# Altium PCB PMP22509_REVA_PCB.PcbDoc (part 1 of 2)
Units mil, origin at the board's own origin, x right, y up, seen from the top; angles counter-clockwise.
Board outline 3681.1 x 1505.91 mil, 2 copper layers (Top Layer, Bottom Layer), stack 62 mil thick; 70 components, 35 nets, 219 pads, 81 vias.
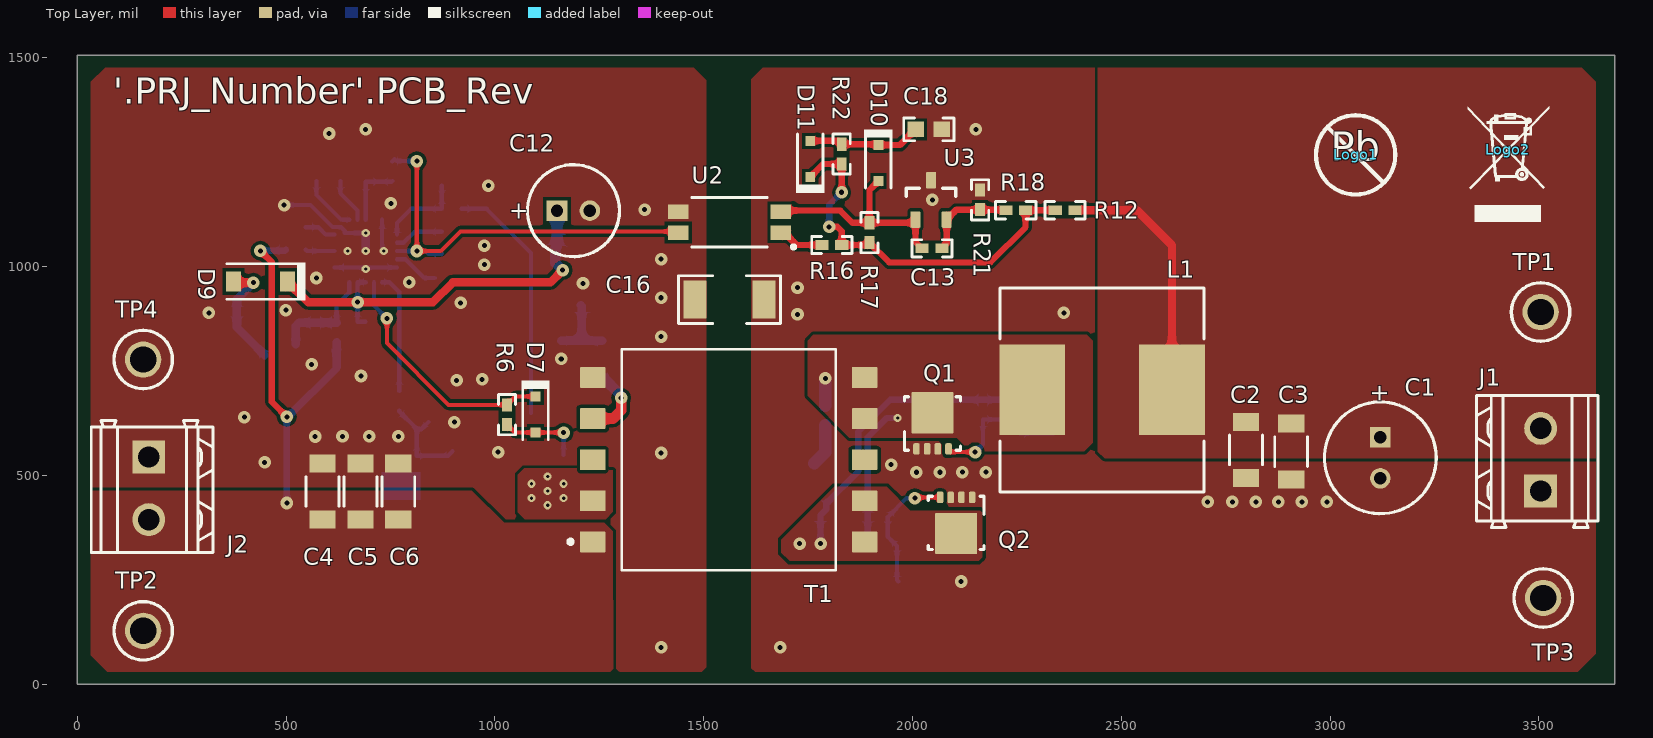
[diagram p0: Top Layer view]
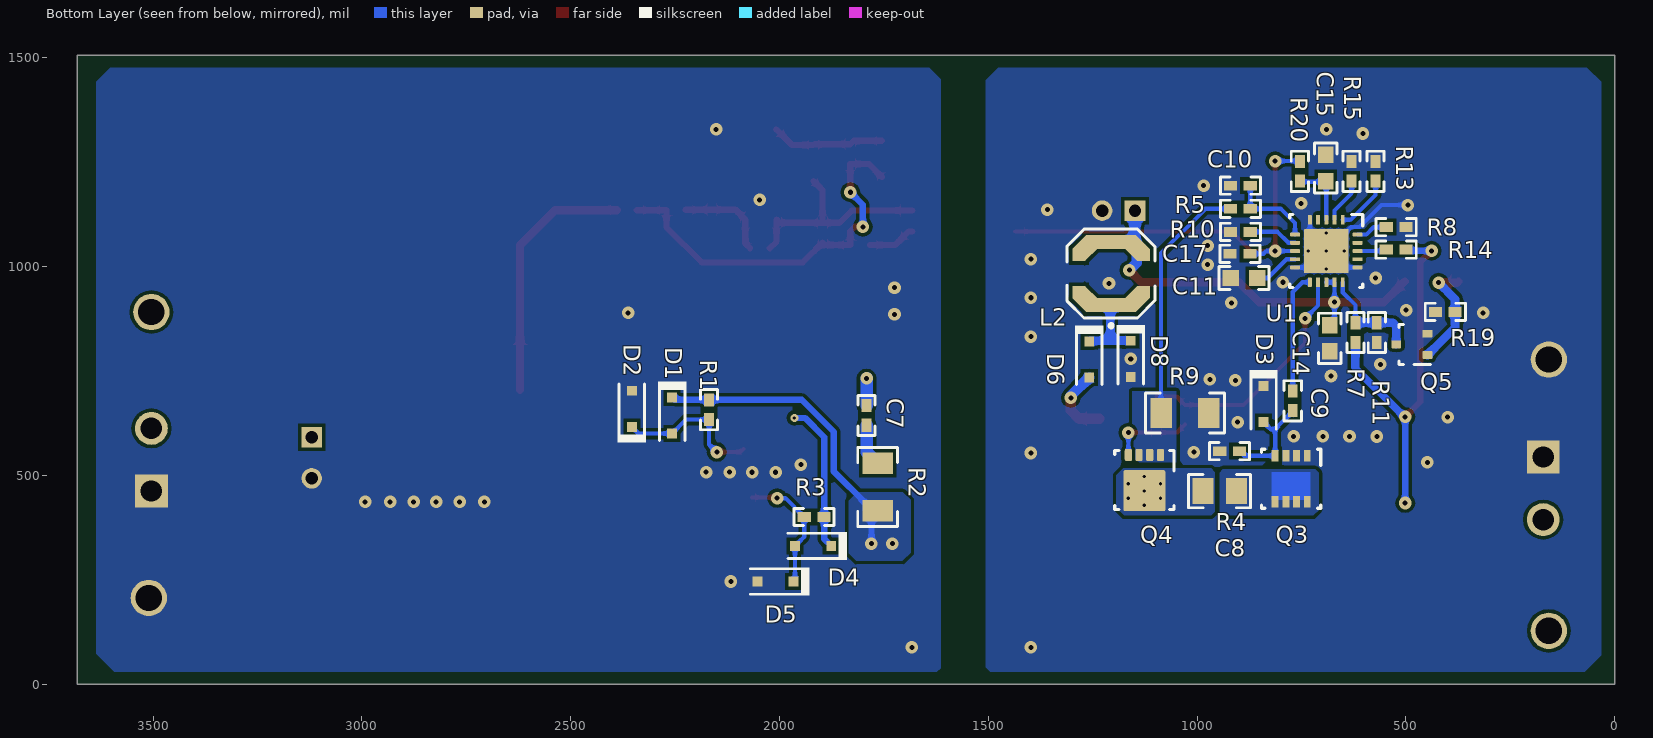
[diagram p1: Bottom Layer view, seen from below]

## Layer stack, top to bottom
Top Solder: solder mask 0.4, Solder Resist, Dk 3.5
Top Layer: signal copper 1.4
Dielectric1: core 59.2, FR-4, Dk 4.8
Bottom Layer: signal copper 1.4
Bottom Solder: solder mask 0.4, Solder Resist, Dk 3.5

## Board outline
0,0 0,1505.91 3681.1,1505.91 3681.1,0

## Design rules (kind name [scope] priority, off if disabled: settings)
AcuteAngle [All] p1: minimum=4.50000000000000E+0001 checktracksonly=FALSE
AssemblyTestPointUsage [All] p1: valid=2
BoardOutlineClearance BoardOutlineClearance_MountingHoles [OnCopper and InComponentClass('Mounting Holes')] p1: gap=25 ignorepadtopadclearanceinfootprint=FALSE
BoardOutlineClearance BoardOutlineClearance_Poly [OnCopper and InPoly] p2: gap=25 ignorepadtopadclearanceinfootprint=FALSE
BoardOutlineClearance [OnCopper and Not InComponentClass('Logo') and not InComponentClass('FiducialMark') and not InRegion(1000,500,4000,800)] p3: gap=25 ignorepadtopadclearanceinfootprint=FALSE
Clearance Clearance_Keepouts [((IsTrack Or IsArc) And Not InPoly) And IsFree and IsKeepOut vs ((IsTrack Or IsArc) And Not InPoly) And IsFree and IsKeepOut] p1: gap=0 ignorepadtopadclearanceinfootprint=FALSE
Clearance Clearance_Poly [InPolygon] p2: gap=8 ignorepadtopadclearanceinfootprint=FALSE except(0: Arc-Hole Track-Hole SMDPad-Hole THPad-Hole Via-Hole Fill-Hole Poly-Hole Region-Hole Text-Hole)
Clearance Clearance_FiducialMark [IsKeepOut and InComponentClass('FiducialMark') vs IsPad and InComponentClass('FiducialMark')] p3: gap=0 ignorepadtopadclearanceinfootprint=FALSE
Clearance [All] p4: gap=7.87 ignorepadtopadclearanceinfootprint=FALSE except(0: Arc-Hole Track-Hole SMDPad-Hole THPad-Hole Via-Hole Fill-Hole Poly-Hole Region-Hole Text-Hole)
ComponentClearance ComponentClearance_MountingHoles_FiducialMarks [InComponentClass('Mounting Holes') vs InComponentClass('FiducialMark')] p1: gap=50 collisioncheckmode=3 verticalgap=10 showdistances=FALSE
ComponentClearance ComponentClearance_Shunt [InComponentClass('Header') vs InComponentClass('Shunt')] p2: gap=0 collisioncheckmode=3 verticalgap=0 showdistances=FALSE
ComponentClearance ComponentClearance_Logo [InComponentClass('Logo')] p3: gap=50 collisioncheckmode=3 verticalgap=10 showdistances=FALSE
ComponentClearance ComponentClearance_ScrewToNut [(HasFootprint('NY PMS 440 0025 PH')) vs (HasFootprint('Keystone_1902C'))] p4: gap=5 collisioncheckmode=3 verticalgap=10 showdistances=FALSE
ComponentClearance ComponentClearance_MountingHoles [InComponentClass('Mounting Holes')] p5: gap=250 collisioncheckmode=3 verticalgap=100000 showdistances=FALSE
ComponentClearance ComponentClearance_SmallPassives [HasFootprint('0201*') or HasFootprint('0402*') or HasFootprint('0508') or HasFootprint('0603*') or HasFootprint('0612') or HasFootprint('0805*') or HasFootprint('0815*') or HasFootprint('0830*') or HasFootprint('1206*') or HasFootprint('1210*') or HasFootprint('1808*') or HasFootprint('1812*') or HasFootprint('1825*') or HasFootprint('2010*') or HasFootprint('2220*') or HasFootprint('2225*') or HasFootprint('2512*') or HasFootprint('2728*') or HasFootprint('3518*') vs HasFootprint('0201*') or HasFootprint('0402*') or HasFootprint('0508') or HasFootprint('0603*') or HasFootprint('0612') or HasFootprint('0805*') or HasFootprint('0815*') or HasFootprint('0830*') or HasFootprint('1206*') or HasFootprint('1210*') or HasFootprint('1808*') or HasFootprint('1812*') or HasFootprint('1825*') or HasFootprint('2010*') or HasFootprint('2220*') or HasFootprint('2225*') or HasFootprint('2512*') or HasFootprint('2728*') or HasFootprint('3518*')] p6: gap=14.96 collisioncheckmode=3 verticalgap=10 showdistances=FALSE
ComponentClearance ComponentClearance_THtoSMT [IsThruComponent vs IsSMTComponent] p7: gap=15 collisioncheckmode=3 verticalgap=30 showdistances=FALSE
ComponentClearance ComponentClearance_THtoTH [IsThruComponent vs IsThruComponent] p8: gap=15 collisioncheckmode=3 verticalgap=30 showdistances=FALSE
ComponentClearance [All] p9: gap=15 collisioncheckmode=3 verticalgap=10 showdistances=FALSE
DiffPairsRouting [All] p1: maxlimit=100 minlimit=10 mostfreqgap=10 toplayer_minwidth=15 toplayer_maxwidth=15 toplayer_prefwidth=15 bottomlayer_minwidth=15 bottomlayer_maxwidth=15 bottomlayer_prefwidth=15 maxuncoupledlength=1000
FabricationTestPointUsage TestPointUsage [All] p1: valid=2 allowmultiple=FALSE
FabricationTestpoint Testpoint [All] p1: side=3 testpointundercomponent=TRUE minsize=40 maxsize=100 preferedsize=60 minholesize=0 maxholesize=40 preferedholesize=32 testpointgrid=1 allowsidetop=TRUE allowsidebottom=TRUE usegrid=TRUE gridtolerance=0.01
FanoutControl Fanout_LCC [IsLCC] p1: bgadir=Out bgaviamode=Centered fanoutstyle=Auto fanoutdirection=Alternating viagrid=1 // Fanout_LCC (Default Rule)
FanoutControl Fanout_BGA [IsBGA] p2: bgadir=Out bgaviamode=Centered fanoutstyle=Auto fanoutdirection=Alternating viagrid=1 // Fanout_BGA (Default Rule)
FanoutControl Fanout_Default [All] p4: bgadir=Out bgaviamode=Centered fanoutstyle=Auto fanoutdirection=Alternating viagrid=1 // Fanout_Default (Default Rule)
FanoutControl Fanout_Small [(CompPinCount < 5)] p5: bgadir=Out bgaviamode=Centered fanoutstyle=Auto fanoutdirection=OutThenIn viagrid=1 // Fanout_Small (Default Rule)
HoleSize [All] p1: absolutevalues=TRUE maxlimit=251 minlimit=7.87 maxpercent=80.000 minpercent=20.000
MinimumAnnularRing MinimumAnnularRing_ThermalPadVias [IsVia and InAnyComponent] p1: minimumring=5.91
MinimumAnnularRing [All] p2: minimumring=8
MinimumSolderMaskSliver MinimumSolderMaskSliver_Logo [InComponentClass('Logo') vs InComponentClass('Logo')] p1: minsoldermaskwidth=0.7
MinimumSolderMaskSliver [All] p2: minsoldermaskwidth=3.94
PlaneConnect [All] p1: planeconnectstyle=Direct reliefexpansion=10 reliefentries=4 reliefconductorwidth=10 reliefairgap=10
PolygonConnect [All] p1: connectstyle=Direct reliefconductorwidth=10 reliefentries=4 polygonreliefangle="90 Angle" airgapwidth=10
RoutingVias ThermalPadVias [IsVia and InAnyComponent] p1: holewidth=7.87 width=19.68 viastyle="Through Hole" minholewidth=7.87 minwidth=19.68 maxholewidth=12.99 maxwidth=23.62
RoutingVias [All] p2: holewidth=16 width=34 viastyle="Through Hole" minholewidth=7.87 minwidth=26 maxholewidth=40 maxwidth=65
SilkToBoardRegionClearance [Not ((IsComment or IsDesignator) And (Hide <> 'False')) and not InRegion(1000,500,4000,800)] p1:
SilkToSilkClearance SilkToSilkClearance_Pb-FreeLogo [(HasFootprint('Pb-Free_Overlay_Medium') OR HasFootprint('Pb-Free_Overlay_Small')) vs (HasFootprint('Pb-Free_Overlay_Medium') OR HasFootprint('Pb-Free_Overlay_Small'))] p1: silktosilkclearance=0
SilkToSilkClearance [All] p2: silktosilkclearance=4
SilkToSolderMaskClearance SilkToComponentPadClearance [IsPad and InAnycomponent] p1: minsilkscreentomaskgap=5 clearancetoexposedcopper=TRUE
SilkToSolderMaskClearance "Silk to Solder Mask Opening" [All] p2: minsilkscreentomaskgap=4 clearancetoexposedcopper=FALSE
SolderMaskExpansion [All] p1: expansion=1.97
Width [All] p1: maxlimit=100 minlimit=6 preferedwidth=10 checkconnectedcopper=TRUE
15 further rules are at their usual default settings.

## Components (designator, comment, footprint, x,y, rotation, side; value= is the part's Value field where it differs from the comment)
C1 "10ZLH330MEFC6.3X11" ZLH_630x1100 3120.08,542.26 r270 top value=330uF
C2 "GRM31CR71A226KE15L" 1206_180 2798.23,561.18 r270 top value=22uF
C3 "GRM31CR71A226KE15L" 1206_180 2906.5,557.15 r270 top value=22uF
C4 "C3216X7R1H475K160AC" 1206_180 587.06,461.69 r90 top value=4.7uF
C5 "C3216X7R1H475K160AC" 1206_180 677.73,461.69 r90 top value=4.7uF
C6 "C3216X7R1H475K160AC" 1206_180 768.68,461.69 r90 top value=4.7uF
C7 "CGA2B2X7R1H102K050BA" 0402 1791.37,643.7 r270 bottom value=1000pF
C8 "GRM21BR72A104KAC4L" 0805_HV 945.87,462.6 r180 bottom value=0.1uF
C9 "GRM155R71E104KE14D" 0402 770.67,678.88 r270 bottom value=0.1uF
C10 "GRM1555C1H101JA01D" 0402 896.09,1193.92 r180 bottom value=100pF
C11 "C1608X7R1H224K080AB" 0603 887.23,972.87 r0 bottom value=0.22uF
C12 "EKMG160ELL101ME11D" Chemi-Con_500x1100 1187.82,1134.13 r0 top value=100uF
C13 "GRM155R71H222KA01D" 0402 2046.54,1043.98 r180 top value=2200pF
C14 "CGA3E1X7R1V105K080AE" 0603 682.09,828.48 r90 bottom value=1uF
C15 "CGA3E1X7R1V105K080AE" 0603 691.58,1236.18 r270 bottom value=1uF
C16 "C1808C272KGRACTU" 1808 1561.64,921.28 r180 top value=2700pF
C17 "CGA2B2X7R1H102K050BA" 0402 897.07,1030.87 r0 bottom value=1000pF
C18 "CGA3E1X7R1V105K080AE" 0603 2038.78,1328.74 r180 top value=1uF
D1 "BAS316,115" SOD-323 2256.89,643.7 r270 bottom value=100V
D2 "SZMM3Z18VST1G" SOD-323 2353.35,659.45 r90 bottom value=18V
D3 "BAS316,115" SOD-323 840.69,671.26 r270 bottom value=100V
D4 "BAS316,115" SOD-323 1919.29,331.18 r0 bottom value=100V
D5 "SZMM3Z18VST1G" SOD-323 2009.18,246.06 r0 bottom value=18V
D6 "BAS316,115" SOD-323 1258,777.9 r270 bottom value=100V
D7 "BAS316,115" SOD-323 1096.95,646.01 r270 top value=100V
D8 "BAS316,115" SOD-323 1158.66,779.43 r270 bottom value=100V
D9 "MMSZ5245B-7-F" SOD-123 438.36,964.57 r180 top value=15V
D10 "BAS316,115" SOD-323 1918.23,1248.03 r270 top value=100V
D11 "BAS316,115" SOD-323 1754.92,1258.01 r90 top value=100V
J1 "691214310002" Wurth_691214310002 3503.94,537.74 r90 top
J2 "691214310002" Wurth_691214310002 170.92,469.32 r270 top
L1 "MSS1278T-472MLB" MSS1278T 2453.74,704.95 r0 top value=4.7uH
L2 "LPS4414-105MLB" LPS4414 1205.57,983.56 r90 bottom value=1mH
Logo1 "Pb-Free Symbol" Pb-Free_Overlay_Medium 3061.02,1267.68 r0 top
Logo2 "WEEE logo" WEEE_Minimum 3425.2,1279.53 r0 top
Q1 "CSD17579Q3A" DNH0008A 2047.64,624.65 r90 top value=30V
Q2 "CSD17579Q3A" DNH0008A 2104.23,386.59 r270 top value=30V
Q3 "FDMC2523P" MLP08S 774.43,492.13 r270 bottom value=-150V
Q4 "CSD19537Q3" DQG0008A 1125.98,489.15 r270 bottom value=100V
Q5 "MMBT3904WT1G" SOT-323 485.6,813.87 r0 bottom value="40 V"
R1 "CRCW040220R0JNED" 0402 2168.31,657.48 r90 bottom value=20
R2 "CRCW120610R0JNEA" 1206 1764.76,472.44 r90 bottom value=10
R3 "CRCW040220R0JNED" 0402 1917.07,400.41 r180 bottom value=20
R4 "CRCW040210K0FKED" 0402 922.07,558.07 r0 bottom value=10.0k
R5 "CRCW04021K00FKED" 0402 896.09,1138.57 r0 bottom value=1.00k
R6 "CRCW040220R0JNED" 0402 1028.95,645.42 r270 top value=20
R7 "CRCW040269K8FKED" 0402 620.67,842.26 r90 bottom value=69.8k
R8 "CRCW040210K0FKED" 0402 523.06,1094.58 r180 bottom value=10.0k
R9 "CSR1206FK75L0" 1206 1028.95,649.61 r0 bottom value=0.075
R10 "CRCW040269K8FKED" 0402 896.09,1083.45 r0 bottom value=69.8k
R11 "CRCW04025K36FKED" 0402 569.48,842.26 r270 bottom value=5.36k
R12 "CRCW04020000Z0ED" 0402 2365.16,1135.13 r180 top value=0
R13 "CRCW040280K6FKED" 0402 572.27,1228.44 r90 bottom value=80.6k
R14 "CRCW04020000Z0ED" 0402 523.06,1040.71 r0 bottom value=0
R15 "CRCW040261K9FKED" 0402 629.75,1228.44 r90 bottom value=61.9k
R16 "CRCW04021K00FKED" 0402 1806.59,1051.86 r0 top value=1.00k
R17 "CRCW040210K0FKED" 0402 1896.57,1081.39 r270 top value=10.0k
R18 "CRCW0402100KFKED" 0402 2247.05,1135.13 r0 top value=100k
R19 "CRCW04021K00FKED" 0402 405.39,891.86 r180 bottom value=1.00k
R20 "CRCW04022K00FKED" 0402 753.77,1228.44 r90 bottom value=2.00k
R21 "CRCW0402100KFKED" 0402 2161.81,1160.13 r270 top value=100k
R22 "CRCW0402100KFKED" 0402 1830.21,1269.68 r270 top value=100k
T1 "WA8515-ALD" FP-WA8515-ALD_SMT_TRANSFORMER_13MM00_13MM46-MFG 1559.67,537.74 r0 top
TP1 "5010" Keystone5010 3503.94,891.4 r0 top
TP2 "5010" Keystone5010 157.48,127.95 r0 top
TP3 "5011" Keystone5011 3510.21,206.69 r0 top
TP4 "5011" Keystone5011 157.48,777.56 r0 top
U1 "UCC2897ARGPR" RGP0020D 690.38,1037.5 r270 bottom
U2 "VOS617A-7X001T" SSOP-4_VISHAY 1561.64,1106.39 r180 top
U3 "TL431LIAIDBZR" DBZ0003A_N 2044.18,1160.13 r90 top

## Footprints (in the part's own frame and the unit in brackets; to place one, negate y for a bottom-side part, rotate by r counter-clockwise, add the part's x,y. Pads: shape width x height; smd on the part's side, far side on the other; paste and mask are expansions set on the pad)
0402 [mm] "0402 from SM-752 data"
  rect 0.8x0.6 smd: 1(-0.6,0) 2(0.6,0)
  silkscreen extent -1.22,-0.52 1.22,0.52, body extent -0.55,-0.3 0.55,0.3, height 0.6
0603 [mm] "0603 from SM-752 data"
  rect 1x0.95 smd: 1(-0.8,0) 2(0.8,0)
  silkscreen extent -1.52,-0.69 1.52,0.69, body extent -0.87,-0.47 0.87,0.47, height 1
0805_HV [mil] "0805 with 30mil clearance between pads"
  rect 50x63 smd: 1(-40,0) 2(40,0)
  silkscreen extent -74,-40 74,40, body extent -43,-29 43,29, height 57
1206 [mm] "1206 from SM-752 data"
  rect 1.3x1.85 smd: 1(-1.45,0) 2(1.45,0)
  silkscreen extent -2.4,-1.21 2.4,1.21, body extent -1.7,-0.9 1.7,0.9, height 1.35
1206_180 [mm] "1206_180"
  rect 1.1x1.6 smd: 1(-1.7,0) 2(1.7,0)
  silkscreen extent -0.9,-1 0.9,1, body extent -1.75,-0.95 1.75,0.95, height 1.8
1808 [mm] "Chip Capacitor, Body 4.6x2.0mm, IPC Medium Density"
  rect 1.4x2.3 smd: 1(-2.1,0) 2(2.1,0)
  silkscreen extent -3.1,-1.45 3.1,1.45, body extent -2.47,-1.2 2.47,1.2, height 2.03
Chemi-Con_500x1100 [mm] "TH, 2-Leads, Dia 5mm, Lead Sapcing 2mm"
  rect 1.25x1.25 hole 0.75: 1(-1,0)
  round 1.25 hole 0.75: 2(1,0)
  silkscreen extent -2.8,-2.8 2.8,2.8, body extent -2.75,-2.75 2.75,2.75, height 12.5
DBZ0003A_N [mm] "SOT23, 3-Leads, Body 2.9x1.3mm, Pitch 0.95mm, Lead Span 2.4mm, IPC Medium Density"
  rrect17% 1x0.6 smd: 1(-1.2,0.95) 2(-1.2,-0.95) 3(1.2,0)
  silkscreen extent 0.2,-1.5 0.7,1.5, body extent -1.26,-1.46 1.26,1.46, height 0.98
DNH0008A [mm] "VSONP-8"
  rrect50% 0.7x0.4 smd paste-0.05 mask-0.05: 1(-1.55,0.975) 2(-1.55,0.325) 3(-1.55,-0.325) 4(-1.55,-0.975) 5(1.55,-0.975) 6(1.55,-0.325) 7(1.55,0.325) 8(1.55,0.975)
  rrect4% 2.51x2.55 smd paste-1.5 mask-1.5: 9(0.645,0)
  rrect14% 0.705x1.125 on Top Paste: 9A(-0.208,0.662) 9B(0.697,0.662) 9C(-0.208,-0.663) 9D(0.697,-0.663)
  silkscreen extent -1.62,-1.7 1.62,1.7, body extent -1.65,-1.65 1.65,1.66, height 0.91
DQG0008A [mm] "SMD, 8-Leads, Body 3.3x3.3mm, Pitch 0.65mm"
  rrect45% 0.75x0.44 smd paste-0.05 mask-0.05: 1(-1.525,0.975) 2(-1.525,0.325) 3(-1.525,-0.325) 4(-1.525,-0.975) 5(1.525,-0.975) 6(1.525,-0.325) 7(1.525,0.325) 8(1.525,0.975)
  rrect15% 0.676x1.125 on Bottom Paste: 9(-0.212,-0.663) 9(-0.212,0.662) 9(0.664,-0.663) 9(0.664,0.662)
  rrect6% 1.775x2.45 on Bottom Solder: 9(0.327,0)
  rrect8% 2.5x2.55 smd paste-1.5 mask-1.5: 9(0.65,0)
  rrect29% 0.5x0.34 on Bottom Solder: 9(1.175,-0.975) 9(1.175,-0.325) 9(1.175,0.325) 9(1.175,0.975)
  silkscreen extent -1.8,-1.8 1.8,1.8, body extent -1.65,-1.65 1.65,1.65, height 1.1
FP-WA8515-ALD_SMT_TRANSFORMER_13MM00_13MM46-MFG [mm]
  rrect8% 1.55x1.27 smd paste+0 mask+0: 1(-8.27,-5) 2(-8.27,-2.5) 3(-8.27,0) 4(-8.27,2.5) 5(-8.27,5) 6(8.27,5) 7(8.27,2.5) 8(8.27,0) 9(8.27,-2.5) 10(8.27,-5)
  silkscreen extent -9.75,-6.73 6.5,6.73, body extent -8.87,-6.73 8.88,6.73, height 12.7
Keystone5010 [mil] "Keystone Multipurpose loops"
  round 87 hole 63: 1(0,0)
  silkscreen extent -70,-70 70,70, body extent -63,-63 63,62, height 319
Keystone5011 [mil] "Keystone Multipurpose loops"
  round 87 hole 63: 1(0,0)
  silkscreen extent -70,-70 70,70, body extent -63,-63 63,62, height 319
LPS4414 [mm] "Coilcraft recommended land pattern Document 548-2 10/1/10"
  rect 0.85x3 smd: 1(-1.925,0) 2(1.925,0)
  rect 1.202x1.07 smd rot 135: 1(-1.55,-1.55) 2(1.55,1.55)
  rect 1.202x1.07 smd rot 45: 1(-1.55,1.55) 2(1.55,-1.55)
  rect 0.75x0.775 smd: 1(-1.125,-1.963) 1(-1.125,1.963) 2(1.125,-1.963) 2(1.125,1.963)
  silkscreen extent -3.26,-2.68 2.7,2.68, body extent -2.2,-2.2 2.2,2.2, height 1.42
MLP08S [mm] "Fairchild MLP08S recommended land pattern"
  rect 0.7x0.42 smd mask+0.051: 1(-1.4,0.975) 2(-1.4,0.325) 3(-1.4,-0.325) 4(-1.4,-0.975) 5(1.4,-0.975) 6(1.4,-0.325) 7(1.4,0.325) 8(1.4,0.975)
  Top Layer region: -0.4,1.185 1.3,1.185 1.3,-1.185 -0.4,-1.185
  silkscreen extent -1.8,-1.8 1.8,1.8, body extent -1.67,-1.67 1.67,1.67, height 0.81
MSS1278T [mm] "Coilcraft recommended land pattern.  Document 598-2 rev 10/20/08"
  rect 4x5.5 smd: 1(-4.25,0) 2(4.25,0)
  silkscreen extent -6.2,-6.2 6.2,6.2, body extent -6.15,-6.15 6.15,6.15, height 8.1
Pb-Free_Overlay_Medium [mil]
  silkscreen extent -95,-95 95,95
RGP0020D [mm] "QFN, 20-Leads, Body 4x4mm, Pitch 0.5mm, Thermal Pad 2.7x2.7mm, TI Recommended"
  rrect42% 0.6x0.24 smd: 1(-1.9,1) 2(-1.9,0.5) 3(-1.9,0) 4(-1.9,-0.5) 5(-1.9,-1) 11(1.9,-1) 12(1.9,-0.5) 13(1.9,0) 14(1.9,0.5) 15(1.9,1)
  rrect42% 0.24x0.6 smd: 6(-1,-1.9) 7(-0.5,-1.9) 8(0,-1.9) 9(0.5,-1.9) 10(1,-1.9) 16(1,1.9) 17(0.5,1.9) 18(0,1.9) 19(-0.5,1.9) 20(-1,1.9)
  rrect8% 1.19x1.19 on Bottom Paste: 21(-0.695,-0.695) 21(-0.695,0.695) 21(0.695,-0.695) 21(0.695,0.695)
  rrect4% 2.7x2.7 smd paste-1.4: 21(0,0)
  silkscreen extent -2.22,-2.22 2.22,2.22, body extent -2.07,-2.07 2.07,2.07, height 1.01
SOD-123 [mm] "On Semi recommended land pattern"
  rect 0.915x1.22 smd: 1(-1.637,0) 2(1.637,0)
  silkscreen extent -2.74,-1.17 2.03,1.17, body extent -1.93,-0.9 1.93,0.9, height 1.35
SOD-323 [mm] "NXP recommended land pattern"
  rect 0.6x0.6 smd paste-0.05: 1(-1.1,0) 2(1.1,0)
  silkscreen extent -2.06,-0.86 1.53,0.86, body extent -1.3,-0.67 1.3,0.68, height 1.1
SOT-323 [mm] "Diodes Inc recommended land pattern.  2016-02-24"
  rrect21% 0.6x0.47 smd: 1(-0.95,0.65) 2(-0.95,-0.65) 3(0.95,0)
  silkscreen extent -1.14,-1.22 0.77,1.22, body extent -1.13,-1.13 1.12,1.12, height 1.13
SSOP-4_VISHAY [mm] "Vishay Recommened"
  rect 1.25x0.9 smd: 1(-3.125,0.635) 2(-3.125,-0.635) 3(3.125,-0.635) 4(3.125,0.635)
  silkscreen extent -3.98,-1.5 2.3,1.59, body extent -3.5,-1.45 3.5,1.45, height 2.42
WEEE_Minimum [mil] "WEEElie bin"
  silkscreen extent -95,-172 99,104
Wurth_691214310002 [mm] "WE"
  rect 2x2 hole 1.3: 1(-1.905,0)
  round 2 hole 1.3: 2(1.905,0)
  silkscreen extent -4.12,-3.5 3.9,3.9, body extent -4.12,-3.5 3.9,3.9, height 8.52
ZLH_630x1100 [mm] "Radial Leaded, 2-Leads, Dia 6.3mm, Height 11mm, Pin Spacing 2.5mm"
  rect 1.25x1.25 hole 0.75: 1(-1.25,0)
  round 1.25 hole 0.75: 2(1.25,0)
  silkscreen extent -3.4,-3.4 3.4,3.4, body extent -3.37,-3.39 3.4,3.39, height 12.51

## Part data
C1: library part CMP-0010285-1, "CAP, AL, 330 uF, 10 V, +/- 20%, 0.094 ohm, TH", Cap_Case=6.3x11mm, Manufacturer=Rubycon, Supplier Part Number 1=1189-1075-ND, Tolerance_%=20%, Value1="0.094 ohm", Value2=10V, ValueDisplayed=330uF
C2 C3: library part CMP-0008959-2, "CAP, CERM, 22 uF, 10 V, +/- 10%, X7R, 1206", Cap_Case=1206, Manufacturer=MuRata, Supplier Part Number 1=490-5309-1-ND, TempCo=X7R, Tolerance_%=10%, Value1=Unknown, Value2=10V, ValueDisplayed=22uF
C4 C5 C6: library part CMP-0008702-2, "CAP, CERM, 4.7 uF, 50 V, +/- 10%, X7R, 1206", Cap_Case=1206_180, Manufacturer=TDK, Supplier Part Number 1=445-8032-1-ND, TempCo=X7R, Tolerance_%=10%, Value1="0.003158 ohm", Value2=50V, ValueDisplayed=4.7uF
C7 C17: library part CMP-0006314-2, "CAP, CERM, 1000 pF, 50 V, +/- 10%, X7R, AEC-Q200 Grade 1, 0402", Cap_Case=0402, Manufacturer=TDK, Supplier Part Number 1=445-5605-1-ND, TempCo=X7R, Tolerance_%=10%, Value1="2.25564 ohm", Value2=50V, ValueDisplayed=1000pF
C8: library part CMP-0008363-2, "CAP, CERM, 0.1 uF, 100 V, +/- 10%, X7R, 0805", Cap_Case=0805, Manufacturer=MuRata, Supplier Part Number 1=490-12005-1-ND, TempCo=X7R, Tolerance_%=10%, Value1=Unknown, Value2=100V, ValueDisplayed=0.1uF
C9: library part CMP-0006659-2, "CAP, CERM, 0.1 uF, 25 V, +/- 10%, X7R, 0402", Cap_Case=0402, Manufacturer=MuRata, Supplier Part Number 1=490-10698-1-ND, TempCo=X7R, Tolerance_%=10%, Value1=Unknown, Value2=25V, ValueDisplayed=0.1uF
C10: library part CMP-0006410-2, "CAP, CERM, 100 pF, 50 V, +/- 5%, C0G/NP0, 0402", Cap_Case=0402, Manufacturer=MuRata, Supplier Part Number 1=81-GRM1555C1H101JA1D, TempCo=C0G/NP0, Tolerance_%=5%, Value1=Unknown, Value2=50V, ValueDisplayed=100pF
C11: library part CMP-0007047-4, "CAP, CERM, 0.22 uF, 50 V, +/- 10%, X7R, 0603", Cap_Case=0603, Manufacturer=TDK, Supplier Part Number 1=445-7408-1-ND, TempCo=X7R, Tolerance_%=10%, Value1="0.021699 ohm", Value2=50V, ValueDisplayed=0.22uF
C12: library part CMP-0010359-1, "CAP, AL, 100 uF, 16 V, +/- 20%, TH", Cap_Case=5x11mm, Manufacturer=Chemi-Con, Supplier Part Number 1=565-1292-ND, Tolerance_%=20%, Value1=Unknown, Value2=16V, ValueDisplayed=100uF
C13: library part CMP-0006683-2, "CAP, CERM, 2200 pF, 50 V, +/- 10%, X7R, 0402", Cap_Case=0402, Manufacturer=MuRata, Supplier Part Number 1=490-1305-1-ND, TempCo=X7R, Tolerance_%=10%, Value1=Unknown, Value2=50V, ValueDisplayed=2200pF
C14 C15 C18: library part CMP-0081259-1, "CAP, CERM, 1 µF, 35 V,+/- 10%, X7R, AEC-Q200 Grade 1, 0603", Cap_Case=0603, Manufacturer=TDK, Supplier Part Number 1=445-174339-1-ND, TempCo=X7R, Tolerance_%=10%, Value2=35V, ValueDisplayed=1µF
C16: library part CMP-0009316-2, "CAP, CERM, 2700 pF, 2000 V, +/- 10%, X7R, 1808", Cap_Case=1808, Manufacturer=Kemet, Supplier Part Number 1=399-4830-1-ND, TempCo=X7R, Tolerance_%=10%, Value1=Unknown, Value2=2000V, ValueDisplayed=2700pF
D1 D3 D4 D6 D7 D8 D10 D11: library part CMP-0029006-2, "Diode, Ultrafast, 100 V, 0.25 A, SOD-323", Manufacturer=Nexperia, Value1=0.25A, Value2=1.4V
D2 D5: library part CMP-0085765-1, "Diode, Zener, 18 V, 300 mW, AEC-Q101, SOD-323", Manufacturer="ON Semiconductor", Power_W=300mW, Value1=0.3W
D9: library part CMP-0005753-4, "Diode, Zener, 15 V, 500 mW, SOD-123", Manufacturer="Diodes Inc.", Power_W=500mW, Value1=0.5W
J1 J2: library part CMP-0054822-2, "Terminal Block, 2x1, 3.81mm, 24-16 AWG, 10A, 300VAC, TH", Manufacturer="Wurth Elektronik"
L1: library part CMP-0060643-1, "Inductor, Shielded Drum Core, Ferrite, 4.7 uH, 6.2 A, 0.01 ohm, SMD", Manufacturer=Coilcraft, Value1="0.01 ohm", Value2=6.2A, ValueDisplayed=4.7uH
L2: library part CMP-0061792-2, "Inductor, Shielded Drum Core, Ferrite, 1 mH, 0.11 A, 16.3 ohm, SMD", Manufacturer=Coilcraft, Value1="16.3 ohm", Value2=0.11A, ValueDisplayed=1mH
Logo1: library part CMP-0074839-1
Logo2: library part CMP-0074769-1
Q1 Q2: library part CMP-0000593-2, "MOSFET, N-CH, 30 V, 20 A, DNH0008A (VSONP-8)", Alternate Manufacturer=None, Manufacturer="Texas Instruments", Supplier Part Number 1=296-39998-1-ND, Value1=0.014, Value2="5.3 nC"
Q3: library part CMP-0000056-3, "MOSFET, P-CH, -150 V, -3 A, QFN-8", Alternate Manufacturer=None, Manufacturer="Fairchild Semiconductor", Value2="6.2 nC"
Q4: library part CMP-0000967-2, "MOSFET, N-CH, 100 V, 50 A, DQG0008A (VSON-CLIP-8)", Alternate Manufacturer=None, Manufacturer="Texas Instruments", Supplier Part Number 1=CSD19537Q3-ND, Value2="16 nC"
Q5: library part CMP-0000404-1, "Transistor, NPN, 40 V, 0.2 A, SOT-323", Manufacturer="ON Semiconductor", Supplier Part Number 1=MMBT3904WT1GOSCT-ND, Value1="0.2 A", Value2=300
R1 R3 R6: library part CMP-0026876-3, "RES, 20, 5%, 0.063 W, AEC-Q200 Grade 0, 0402", Manufacturer=Vishay-Dale, Power_W=63mW, Supplier Part Number 1=541-20JCT-ND, TempCo="200 ppm/C", Tolerance_%=5%, Value2=0.063W, Value_Code=20R0, ValueDisplayed=20
R2: library part CMP-0018578-3, "RES, 10, 5%, 0.25 W, AEC-Q200 Grade 0, 1206", Manufacturer=Vishay-Dale, Power_W=250mW, Supplier Part Number 1=541-10ECT-ND, TempCo="200 ppm/C", Tolerance_%=5%, Value2=0.25W, Value_Code=10R0, ValueDisplayed=10
R4 R8 R17: library part CMP-0025958-3, "RES, 10.0 k, 1%, 0.063 W, AEC-Q200 Grade 0, 0402", Manufacturer=Vishay-Dale, Power_W=63mW, Supplier Part Number 1=541-10.0KLCT-ND, TempCo="100 ppm/C", Tolerance_%=1%, Value2=0.063W, Value_Code=10k0, ValueDisplayed=10.0k
R5 R16 R19: library part CMP-0026071-3, "RES, 1.00 k, 1%, 0.063 W, AEC-Q200 Grade 0, 0402", Manufacturer=Vishay-Dale, Power_W=63mW, Supplier Part Number 1=541-1.00KLCT-ND, TempCo="100 ppm/C", Tolerance_%=1%, Value2=0.063W, Value_Code=1k00, ValueDisplayed=1.00k
R7 R10: library part CMP-0026510-2, "RES, 69.8 k, 1%, 0.063 W, AEC-Q200 Grade 0, 0402", Manufacturer=Vishay-Dale, Power_W=63mW, Supplier Part Number 1=541-69.8KLCT-ND, TempCo="100 ppm/C", Tolerance_%=1%, Value2=0.063W, Value_Code=69k8, ValueDisplayed=69.8k
R9: library part CMP-0017264-2, "RES, 0.075, 1%, 0.5 W, 1206", Manufacturer="Stackpole Electronics Inc", Power_W=500mW, Supplier Part Number 1=CSR1206FK75L0CT-ND, TempCo="100 ppm/C", Tolerance_%=1%, Value2=0.5W, Value_Code=R075, ValueDisplayed=0.075
R11: library part CMP-0026465-2, "RES, 5.36 k, 1%, 0.063 W, AEC-Q200 Grade 0, 0402", Manufacturer=Vishay-Dale, Power_W=63mW, Supplier Part Number 1=541-5.36KLCT-ND, TempCo="100 ppm/C", Tolerance_%=1%, Value2=0.063W, Value_Code=5k36, ValueDisplayed=5.36k
R12 R14: library part CMP-0026822-3, "RES, 0, 5%, 0.063 W, AEC-Q200 Grade 0, 0402", Manufacturer=Vishay-Dale, Power_W=63mW, Supplier Part Number 1=541-0.0JCT-ND, TempCo="200 ppm/C", Tolerance_%=5%, Value2=0.063W, Value_Code=0000, ValueDisplayed=0
R13: library part CMP-0026570-2, "RES, 80.6 k, 1%, 0.063 W, AEC-Q200 Grade 0, 0402", Manufacturer=Vishay-Dale, Power_W=63mW, Supplier Part Number 1=541-80.6KLCT-ND, TempCo="100 ppm/C", Tolerance_%=1%, Value2=0.063W, Value_Code=80k6, ValueDisplayed=80.6k
R15: library part CMP-0026490-2, "RES, 61.9 k, 1%, 0.063 W, AEC-Q200 Grade 0, 0402", Manufacturer=Vishay-Dale, Power_W=63mW, Supplier Part Number 1=541-61.9KLCT-ND, TempCo="100 ppm/C", Tolerance_%=1%, Value2=0.063W, Value_Code=61k9, ValueDisplayed=61.9k
R18 R21 R22: library part CMP-0025950-3, "RES, 100 k, 1%, 0.063 W, AEC-Q200 Grade 0, 0402", Manufacturer=Vishay-Dale, Power_W=63mW, Supplier Part Number 1=541-100KLCT-ND, TempCo="100 ppm/C", Tolerance_%=1%, Value2=0.063W, Value_Code=100k
R20: library part CMP-0026227-2, "RES, 2.00 k, 1%, 0.063 W, AEC-Q200 Grade 0, 0402", Manufacturer=Vishay-Dale, Power_W=63mW, Supplier Part Number 1=541-2.00KLCT-ND, TempCo="100 ppm/C", Tolerance_%=1%, Value2=0.063W, Value_Code=2k00, ValueDisplayed=2.00k
T1: library part CMP-0088844-1, "25 W Forward Mode Transformer  for TPS23754", Manufacturer=Coilcraft, Operating Temperature Range=to, Voltage_Isolation_Vrms=1500Vrms
TP1 TP2: library part CMP-0055147-1, "Test Point, Multipurpose, Red, TH", Color=Red, Manufacturer=Keystone, Supplier Part Number 1=36-5010-ND
TP3 TP4: library part CMP-0055148-1, "Test Point, Multipurpose, Black, TH", Color=Black, Manufacturer=Keystone, Supplier Part Number 1=36-5011-ND
U1: library part CMP-0031996-2, "Advanced Active Clamp PWM Controller with Current Control, -40 to +125 degC, 20-pin QFN (RGP), Green (RoHS & no Sb/Br)", Frequency(Max)(kHz)=1000, Manufacturer="Texas Instruments", Rating=Catalog
U2: library part CMP-0006163-3, "Optocoupler, 3.75 kV, 80-160% CTR, SMT", Manufacturer=Vishay-Semiconductor, Supplier Part Number 1=VOS617A-7X001T-ND, Voltage_Isolation_Vrms=3.75kV
U3: library part CMP-0084729-1, "Programmable Shunt Regulator with Optimized Reference Current, DBZ0003A (SOT-23-3)", Alternate Manufacturer="Texas Instruments"

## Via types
v1: diameter 30, hole 12, Top Layer to Bottom Layer, 65 vias
v2: diameter 19.68, hole 7.87, Top Layer to Bottom Layer, 12 vias
v3: diameter 30, hole 12, Top Layer to Bottom Layer, tented both sides, 3 vias
v4: diameter 19.68, hole 7.87, Top Layer to Bottom Layer, tented both sides, 1 vias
